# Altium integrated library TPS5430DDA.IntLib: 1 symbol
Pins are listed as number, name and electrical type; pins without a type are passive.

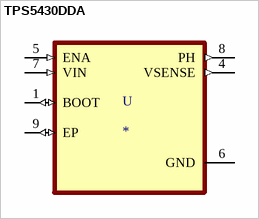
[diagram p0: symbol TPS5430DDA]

## TPS5430DDA
designator U
5.5Vè‡³36Vè¾“å…¥ï¼Œ3Aï¼Œ500kHzé™åŽ‹è½¬æ¢å™¨; MF: Texas Instruments; MP: TPS5430DDA
footprint VREG_LM5017MR/NOPB
pins: 1 BOOT (io), 4 VSENSE (out), 5 ENA (in), 6 GND (power), 7 VIN (in), 8 PH (out), 9 EP (io)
